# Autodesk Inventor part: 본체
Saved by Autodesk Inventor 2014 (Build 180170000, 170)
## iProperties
Created: 2026-07
Part Number: 본체
Material: 알루미늄 6061
Document SubType Name: Modeling
Designer: dg
Density: 2.71 g/cm^3
Appearance: 알루미늄 - 평지
Author: jhkim
Creation Date: 2026-07-02
Sending System: Autodesk Inventor 2027
Preprocessor: ST-DEVELOPER v20.1
Author: dg
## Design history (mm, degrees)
node "본체1"
node "솔리드1"
node "기준1"
